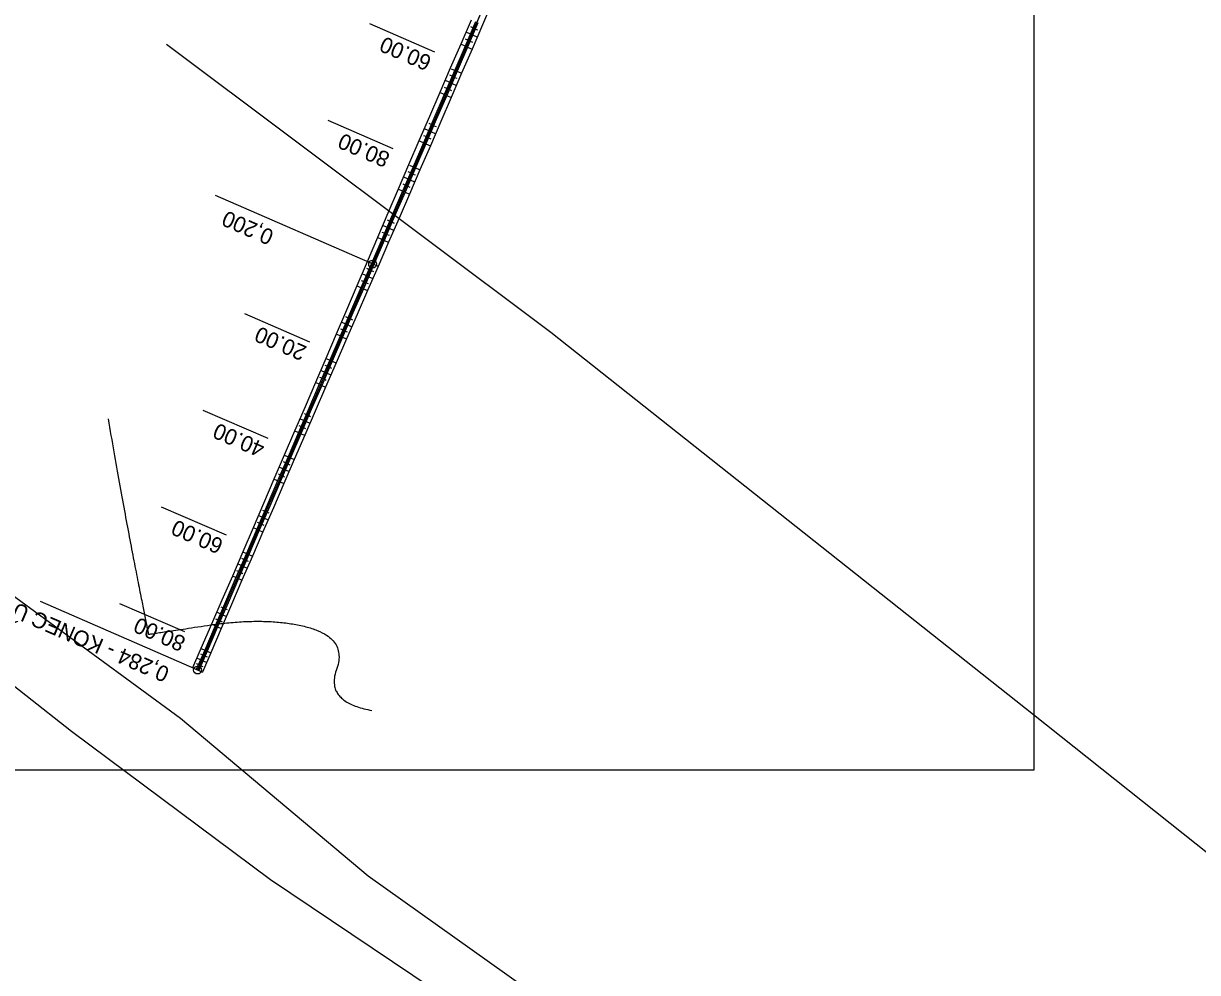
# Model space of a CAD drawing. Extents: x -495905 to -478420, y -1113297 to -1107716.
# Drawn here: x -480652.7 to -480429.6, y -1112691.6 to -1112511.2 of the extents above; entities that cross this region are included whole.
import ezdxf

# ---------------------------------------------------------------- set-up
doc = ezdxf.new("R2010")
doc.units = 0
for name, color, linetype in [('05_VHO_PŘÍKOP_NÁVRH', 7, 'Continuous'), ('2D_VRSTEVNICE', 7, 'Continuous'), ('Implicitní', 7, 'Continuous'), ('O6_HATCH_SLOPE_L', 7, 'Continuous'), ('O6_HATCH_SLOPE_R', 7, 'Continuous'), ('O6_HECTOMETRY', 7, 'Continuous'), ('O6_HLBODY', 7, 'Continuous'), ('O6_HRANA_TELESO', 7, 'Continuous'), ('O6_OSA', 7, 'Continuous'), ('O6_STANICENI', 7, 'Continuous'), ('O6_VOZOVKA', 7, 'Continuous'), ('O6_ZPEVKRAJ', 7, 'Continuous'), ('ODVODNĚNÍ PLOŠNÉ', 7, 'Continuous'), ('zamereni', 7, 'Continuous')]:
    doc.layers.add(name, color=color, linetype=linetype)

msp = doc.modelspace()

# ---------------------------------------------------------------- linework, layer by layer
at = {"layer": '05_VHO_PŘÍKOP_NÁVRH'}
msp.add_lwpolyline([(-480509.98, -1112372.25), (-480517.54, -1112397.37), (-480619.64, -1112634.1)], dxfattribs=at)
at = {"layer": '2D_VRSTEVNICE'}
msp.add_open_spline([(-480636.65, -1112586.38), (-480633.52, -1112604.4), (-480628.99, -1112627.3), (-480628.99, -1112627.3), (-480628.99, -1112627.3), (-480628.99, -1112627.3), (-480606.33, -1112623.9), (-480591.03, -1112628.04), (-480595.46, -1112640.12), (-480586.52, -1112641.78)], degree=2, dxfattribs=at)
at = {"layer": 'Implicitní'}
msp.add_lwpolyline([(-480696.42, -1112347.24), (-480460.69, -1112347.24), (-480460.69, -1112653.1), (-480696.42, -1112653.1)], close=True, dxfattribs=at)
at = {"layer": 'O6_HATCH_SLOPE_L'}
for p, q in [((-480567.31, -1112513.43), (-480566.48, -1112513.79)), ((-480566.82, -1112512.28), (-480566.4, -1112512.46)), ((-480565.98, -1112512.64), (-480565.98, -1112512.64)), ((-480568.3, -1112515.72), (-480567.46, -1112516.08)), ((-480567.81, -1112514.58), (-480567.39, -1112514.76)), ((-480566.97, -1112514.94), (-480566.97, -1112514.94)), ((-480571.27, -1112522.61), (-480570.42, -1112522.98)), ((-480570.78, -1112521.46), (-480570.35, -1112521.64)), ((-480569.93, -1112521.83), (-480569.93, -1112521.83)), ((-480572.26, -1112524.91), (-480571.41, -1112525.27)), ((-480571.77, -1112523.76), (-480571.34, -1112523.94)), ((-480570.92, -1112524.12), (-480570.92, -1112524.12)), ((-480574.74, -1112530.65), (-480574.31, -1112530.83)), ((-480573.89, -1112531.01), (-480573.89, -1112531.01)), ((-480575.73, -1112532.94), (-480575.3, -1112533.12)), ((-480575.23, -1112531.79), (-480574.38, -1112532.16)), ((-480574.88, -1112533.31), (-480574.88, -1112533.31)), ((-480576.22, -1112534.09), (-480575.38, -1112534.45)), ((-480578.7, -1112539.83), (-480578.28, -1112540.01)), ((-480577.86, -1112540.19), (-480577.86, -1112540.19)), ((-480579.69, -1112542.12), (-480579.27, -1112542.3)), ((-480579.19, -1112540.98), (-480578.35, -1112541.34)), ((-480578.85, -1112542.48), (-480578.85, -1112542.48)), ((-480580.18, -1112543.27), (-480579.35, -1112543.63)), ((-480582.66, -1112549.01), (-480582.25, -1112549.19)), ((-480581.83, -1112549.36), (-480581.83, -1112549.36)), ((-480583.65, -1112551.3), (-480583.24, -1112551.48)), ((-480583.15, -1112550.16), (-480582.33, -1112550.51)), ((-480582.83, -1112551.66), (-480582.83, -1112551.66)), ((-480584.14, -1112552.45), (-480583.33, -1112552.8)), ((-480586.62, -1112558.19), (-480586.22, -1112558.36)), ((-480587.61, -1112560.49), (-480587.21, -1112560.66)), ((-480587.11, -1112559.34), (-480586.32, -1112559.68)), ((-480585.82, -1112558.53), (-480585.82, -1112558.53)), ((-480588.1, -1112561.64), (-480587.32, -1112561.97)), ((-480586.82, -1112560.83), (-480586.82, -1112560.83)), ((-480591.07, -1112568.52), (-480590.31, -1112568.85)), ((-480590.58, -1112567.37), (-480590.2, -1112567.54)), ((-480589.81, -1112567.71), (-480589.81, -1112567.71)), ((-480592.06, -1112570.82), (-480591.31, -1112571.14)), ((-480591.57, -1112569.67), (-480591.19, -1112569.83)), ((-480590.81, -1112570), (-480590.81, -1112570)), ((-480595.03, -1112577.7), (-480594.29, -1112578.02)), ((-480594.54, -1112576.56), (-480594.17, -1112576.72)), ((-480593.8, -1112576.88), (-480593.8, -1112576.88)), ((-480596.02, -1112580), (-480595.29, -1112580.32)), ((-480595.53, -1112578.85), (-480595.16, -1112579.01)), ((-480594.79, -1112579.17), (-480594.79, -1112579.17)), ((-480598.99, -1112586.89), (-480598.27, -1112587.2)), ((-480598.5, -1112585.74), (-480598.14, -1112585.9)), ((-480597.77, -1112586.05), (-480597.77, -1112586.05)), ((-480599.98, -1112589.18), (-480599.27, -1112589.49)), ((-480599.49, -1112588.03), (-480599.13, -1112588.19)), ((-480598.77, -1112588.35), (-480598.77, -1112588.35)), ((-480602.95, -1112596.07), (-480602.25, -1112596.37)), ((-480602.46, -1112594.92), (-480602.1, -1112595.07)), ((-480601.75, -1112595.23), (-480601.75, -1112595.23)), ((-480603.94, -1112598.36), (-480603.24, -1112598.67)), ((-480603.45, -1112597.22), (-480603.1, -1112597.37)), ((-480602.74, -1112597.52), (-480602.74, -1112597.52)), ((-480606.92, -1112605.25), (-480606.23, -1112605.55)), ((-480606.42, -1112604.1), (-480606.07, -1112604.25)), ((-480605.73, -1112604.4), (-480605.73, -1112604.4)), ((-480607.41, -1112606.4), (-480607.07, -1112606.55)), ((-480606.72, -1112606.7), (-480606.72, -1112606.7)), ((-480607.91, -1112607.55), (-480607.22, -1112607.84)), ((-480610.38, -1112613.29), (-480610.04, -1112613.43)), ((-480609.71, -1112613.58), (-480609.71, -1112613.58)), ((-480611.37, -1112615.58), (-480611.03, -1112615.73)), ((-480610.88, -1112614.43), (-480610.2, -1112614.73)), ((-480610.7, -1112615.87), (-480610.7, -1112615.87)), ((-480611.86, -1112616.73), (-480611.19, -1112617.02)), ((-480614.34, -1112622.47), (-480613.99, -1112622.62)), ((-480613.65, -1112622.77), (-480613.65, -1112622.77)), ((-480615.33, -1112624.76), (-480614.98, -1112624.91)), ((-480614.84, -1112623.62), (-480614.14, -1112623.92)), ((-480614.63, -1112625.06), (-480614.63, -1112625.06)), ((-480615.83, -1112625.91), (-480615.12, -1112626.22)), ((-480618.2, -1112631.43), (-480617.84, -1112631.58)), ((-480617.48, -1112631.74), (-480617.48, -1112631.74)), ((-480619.4, -1112634.19), (-480618.67, -1112634.51)), ((-480619, -1112633.27), (-480618.64, -1112633.43)), ((-480618.6, -1112632.35), (-480617.88, -1112632.66)), ((-480618.27, -1112633.58), (-480618.27, -1112633.58))]:
    msp.add_line(p, q, dxfattribs=at)
at = {"layer": 'O6_HATCH_SLOPE_R'}
for p, q in [((-480567.79, -1112513.22), (-480568.62, -1112512.86)), ((-480568.13, -1112511.72), (-480568.13, -1112511.72)), ((-480567.29, -1112512.07), (-480567.71, -1112511.89)), ((-480568.78, -1112515.52), (-480569.62, -1112515.16)), ((-480569.12, -1112514.01), (-480569.12, -1112514.01)), ((-480568.28, -1112514.37), (-480568.7, -1112514.19)), ((-480571.75, -1112522.4), (-480572.6, -1112522.04)), ((-480572.1, -1112520.89), (-480572.1, -1112520.89)), ((-480571.25, -1112521.26), (-480571.68, -1112521.07)), ((-480572.74, -1112524.7), (-480573.59, -1112524.33)), ((-480573.09, -1112523.19), (-480573.09, -1112523.19)), ((-480572.24, -1112523.55), (-480572.67, -1112523.37)), ((-480575.71, -1112531.59), (-480576.56, -1112531.22)), ((-480576.07, -1112530.07), (-480576.07, -1112530.07)), ((-480575.22, -1112530.44), (-480575.64, -1112530.26)), ((-480576.7, -1112533.88), (-480577.55, -1112533.52)), ((-480577.05, -1112532.37), (-480577.05, -1112532.37)), ((-480576.21, -1112532.73), (-480576.63, -1112532.55)), ((-480579.67, -1112540.77), (-480580.51, -1112540.41)), ((-480580.02, -1112539.26), (-480580.02, -1112539.26)), ((-480579.17, -1112539.62), (-480579.6, -1112539.44)), ((-480580.66, -1112543.06), (-480581.5, -1112542.7)), ((-480581, -1112541.56), (-480581, -1112541.56)), ((-480580.17, -1112541.92), (-480580.58, -1112541.74)), ((-480583.96, -1112548.45), (-480583.96, -1112548.45)), ((-480583.14, -1112548.8), (-480583.55, -1112548.63)), ((-480584.94, -1112550.75), (-480584.94, -1112550.75)), ((-480584.12, -1112551.1), (-480584.53, -1112550.92)), ((-480583.63, -1112549.95), (-480584.45, -1112549.6)), ((-480584.62, -1112552.25), (-480585.43, -1112551.9)), ((-480587.89, -1112557.64), (-480587.89, -1112557.64)), ((-480587.1, -1112557.99), (-480587.49, -1112557.81)), ((-480588.88, -1112559.94), (-480588.88, -1112559.94)), ((-480588.09, -1112560.28), (-480588.48, -1112560.11)), ((-480587.59, -1112559.13), (-480588.38, -1112558.79)), ((-480588.58, -1112561.43), (-480589.37, -1112561.09)), ((-480591.82, -1112566.84), (-480591.82, -1112566.84)), ((-480591.06, -1112567.17), (-480591.44, -1112567)), ((-480592.81, -1112569.14), (-480592.81, -1112569.14)), ((-480592.05, -1112569.46), (-480592.43, -1112569.3)), ((-480591.55, -1112568.32), (-480592.31, -1112567.99)), ((-480592.54, -1112570.61), (-480593.3, -1112570.29)), ((-480595.76, -1112576.03), (-480595.76, -1112576.03)), ((-480595.02, -1112576.35), (-480595.39, -1112576.19)), ((-480596.75, -1112578.33), (-480596.75, -1112578.33)), ((-480596.01, -1112578.65), (-480596.38, -1112578.49)), ((-480595.51, -1112577.5), (-480596.25, -1112577.18)), ((-480596.5, -1112579.79), (-480597.24, -1112579.48)), ((-480599.47, -1112586.68), (-480600.2, -1112586.37)), ((-480599.7, -1112585.22), (-480599.7, -1112585.22)), ((-480598.98, -1112585.53), (-480599.34, -1112585.38)), ((-480600.46, -1112588.98), (-480601.18, -1112588.67)), ((-480600.69, -1112587.52), (-480600.69, -1112587.52)), ((-480599.97, -1112587.83), (-480600.33, -1112587.67)), ((-480603.43, -1112595.86), (-480604.14, -1112595.56)), ((-480603.65, -1112594.41), (-480603.65, -1112594.41)), ((-480602.94, -1112594.72), (-480603.29, -1112594.56)), ((-480604.42, -1112598.16), (-480605.13, -1112597.85)), ((-480604.63, -1112596.71), (-480604.63, -1112596.71)), ((-480603.93, -1112597.01), (-480604.28, -1112596.86)), ((-480607.39, -1112605.05), (-480608.08, -1112604.75)), ((-480607.59, -1112603.6), (-480607.59, -1112603.6)), ((-480606.9, -1112603.9), (-480607.24, -1112603.75)), ((-480608.38, -1112607.34), (-480609.07, -1112607.05)), ((-480608.58, -1112605.9), (-480608.58, -1112605.9)), ((-480607.89, -1112606.19), (-480608.23, -1112606.04)), ((-480611.35, -1112614.23), (-480612.02, -1112613.94)), ((-480611.53, -1112612.79), (-480611.53, -1112612.79)), ((-480610.86, -1112613.08), (-480611.19, -1112612.93)), ((-480612.34, -1112616.52), (-480613.01, -1112616.24)), ((-480612.52, -1112615.09), (-480612.52, -1112615.09)), ((-480611.85, -1112615.38), (-480612.18, -1112615.23)), ((-480615.31, -1112623.41), (-480615.99, -1112623.12)), ((-480615.49, -1112621.97), (-480615.49, -1112621.97)), ((-480614.82, -1112622.26), (-480615.16, -1112622.12)), ((-480616.49, -1112624.26), (-480616.49, -1112624.26)), ((-480615.81, -1112624.56), (-480616.15, -1112624.41)), ((-480616.3, -1112625.71), (-480616.99, -1112625.41)), ((-480619.08, -1112632.14), (-480619.79, -1112631.84)), ((-480619.39, -1112630.92), (-480619.39, -1112630.92)), ((-480618.68, -1112631.22), (-480619.03, -1112631.07)), ((-480619.88, -1112633.99), (-480620.59, -1112633.68)), ((-480620.19, -1112632.76), (-480620.19, -1112632.76)), ((-480619.48, -1112633.07), (-480619.83, -1112632.91))]:
    msp.add_line(p, q, dxfattribs=at)
at = {"layer": 'O6_HECTOMETRY'}
msp.add_circle((-480586.36, -1112556.94), 0.75, dxfattribs=at)
at = {"layer": 'O6_HLBODY'}
for p, q in [((-480585.39, -1112557.35), (-480616.24, -1112543.93)), ((-480618.67, -1112634.51), (-480649.51, -1112621.09))]:
    msp.add_line(p, q, dxfattribs=at)
msp.add_circle((-480619.64, -1112634.1), 0.75, dxfattribs=at)
at = {"layer": 'O6_HRANA_TELESO'}
for p, q in [((-480563.52, -1112506.9), (-480565.49, -1112511.49)), ((-480567.63, -1112510.57), (-480569.62, -1112515.16)), ((-480565.49, -1112511.49), (-480567.46, -1112516.08)), ((-480569.62, -1112515.16), (-480571.6, -1112519.74)), ((-480567.46, -1112516.08), (-480569.44, -1112520.68)), ((-480571.6, -1112519.74), (-480573.59, -1112524.33)), ((-480569.44, -1112520.68), (-480571.41, -1112525.27)), ((-480573.59, -1112524.33), (-480575.57, -1112528.92)), ((-480571.41, -1112525.27), (-480573.39, -1112529.86)), ((-480575.57, -1112528.92), (-480577.55, -1112533.52)), ((-480573.39, -1112529.86), (-480575.38, -1112534.45)), ((-480577.55, -1112533.52), (-480579.52, -1112538.11)), ((-480575.38, -1112534.45), (-480577.36, -1112539.04)), ((-480579.52, -1112538.11), (-480581.5, -1112542.7)), ((-480577.36, -1112539.04), (-480579.35, -1112543.63)), ((-480581.5, -1112542.7), (-480583.47, -1112547.3)), ((-480579.35, -1112543.63), (-480581.34, -1112548.22)), ((-480583.47, -1112547.3), (-480585.43, -1112551.9)), ((-480581.34, -1112548.22), (-480583.33, -1112552.8)), ((-480585.43, -1112551.9), (-480587.4, -1112556.49)), ((-480583.33, -1112552.8), (-480585.32, -1112557.39)), ((-480587.4, -1112556.49), (-480589.37, -1112561.09)), ((-480585.32, -1112557.39), (-480587.32, -1112561.97)), ((-480589.37, -1112561.09), (-480591.33, -1112565.69)), ((-480587.32, -1112561.97), (-480589.31, -1112566.56)), ((-480591.33, -1112565.69), (-480593.3, -1112570.29)), ((-480589.31, -1112566.56), (-480591.31, -1112571.14)), ((-480593.3, -1112570.29), (-480595.27, -1112574.88)), ((-480591.31, -1112571.14), (-480593.3, -1112575.73)), ((-480595.27, -1112574.88), (-480597.24, -1112579.48)), ((-480593.3, -1112575.73), (-480595.29, -1112580.32)), ((-480597.24, -1112579.48), (-480599.21, -1112584.07)), ((-480595.29, -1112580.32), (-480597.28, -1112584.91)), ((-480599.21, -1112584.07), (-480601.18, -1112588.67)), ((-480597.28, -1112584.91), (-480599.27, -1112589.49)), ((-480601.18, -1112588.67), (-480603.15, -1112593.26)), ((-480599.27, -1112589.49), (-480601.25, -1112594.08)), ((-480603.15, -1112593.26), (-480605.13, -1112597.85)), ((-480601.25, -1112594.08), (-480603.24, -1112598.67)), ((-480605.13, -1112597.85), (-480607.1, -1112602.45)), ((-480603.24, -1112598.67), (-480605.23, -1112603.26)), ((-480607.1, -1112602.45), (-480609.07, -1112607.05)), ((-480605.23, -1112603.26), (-480607.22, -1112607.84)), ((-480609.07, -1112607.05), (-480611.04, -1112611.64)), ((-480607.22, -1112607.84), (-480609.21, -1112612.43)), ((-480611.04, -1112611.64), (-480613.01, -1112616.24)), ((-480609.21, -1112612.43), (-480611.19, -1112617.02)), ((-480613.01, -1112616.24), (-480615, -1112620.82)), ((-480611.19, -1112617.02), (-480613.16, -1112621.62)), ((-480615, -1112620.82), (-480616.99, -1112625.41)), ((-480613.16, -1112621.62), (-480615.12, -1112626.22)), ((-480616.99, -1112625.41), (-480618.99, -1112629.99)), ((-480615.12, -1112626.22), (-480617.09, -1112630.81)), ((-480618.99, -1112629.99), (-480620.59, -1112633.68)), ((-480617.09, -1112630.81), (-480618.67, -1112634.51))]:
    msp.add_line(p, q, dxfattribs=at)
at = {"layer": 'O6_OSA'}
msp.add_line((-480519.82, -1112402.65), (-480619.64, -1112634.1), dxfattribs=at)
at = {"layer": 'O6_STANICENI'}
for p, q in [((-480574.52, -1112516.66), (-480586.92, -1112511.32)), ((-480571.44, -1112519.82), (-480569.6, -1112520.61)), ((-480582.44, -1112535.03), (-480594.84, -1112529.68)), ((-480579.36, -1112538.18), (-480577.52, -1112538.97)), ((-480598.29, -1112571.76), (-480610.68, -1112566.41)), ((-480595.2, -1112574.91), (-480593.36, -1112575.7)), ((-480606.21, -1112590.12), (-480618.6, -1112584.78)), ((-480603.12, -1112593.27), (-480601.29, -1112594.07)), ((-480614.13, -1112608.49), (-480626.52, -1112603.14)), ((-480611.04, -1112611.64), (-480609.21, -1112612.43)), ((-480622.05, -1112626.85), (-480634.44, -1112621.51)), ((-480618.96, -1112630), (-480617.13, -1112630.8)), ((-480620.55, -1112633.7), (-480618.72, -1112634.49))]:
    msp.add_line(p, q, dxfattribs=at)
at = {"layer": 'O6_VOZOVKA'}
for p, q in [((-480566.79, -1112510.93), (-480568.77, -1112515.52)), ((-480566.33, -1112511.13), (-480568.31, -1112515.72)), ((-480568.77, -1112515.52), (-480570.75, -1112520.11)), ((-480568.31, -1112515.72), (-480570.29, -1112520.31)), ((-480570.75, -1112520.11), (-480572.73, -1112524.7)), ((-480570.29, -1112520.31), (-480572.27, -1112524.9)), ((-480572.73, -1112524.7), (-480574.71, -1112529.29)), ((-480572.27, -1112524.9), (-480574.25, -1112529.49)), ((-480574.71, -1112529.29), (-480576.69, -1112533.89)), ((-480574.25, -1112529.49), (-480576.23, -1112534.08)), ((-480576.69, -1112533.89), (-480578.67, -1112538.48)), ((-480576.23, -1112534.08), (-480578.21, -1112538.68)), ((-480578.67, -1112538.48), (-480580.65, -1112543.07)), ((-480578.21, -1112538.68), (-480580.19, -1112543.27)), ((-480580.65, -1112543.07), (-480582.63, -1112547.66)), ((-480580.19, -1112543.27), (-480582.17, -1112547.86)), ((-480582.63, -1112547.66), (-480584.61, -1112552.25)), ((-480582.17, -1112547.86), (-480584.15, -1112552.45)), ((-480584.61, -1112552.25), (-480586.59, -1112556.84)), ((-480584.15, -1112552.45), (-480586.13, -1112557.04)), ((-480586.59, -1112556.84), (-480588.57, -1112561.43)), ((-480586.13, -1112557.04), (-480588.11, -1112561.63)), ((-480588.57, -1112561.43), (-480590.55, -1112566.02)), ((-480588.11, -1112561.63), (-480590.09, -1112566.22)), ((-480590.55, -1112566.02), (-480592.53, -1112570.62)), ((-480590.09, -1112566.22), (-480592.07, -1112570.81)), ((-480592.53, -1112570.62), (-480594.51, -1112575.21)), ((-480592.07, -1112570.81), (-480594.05, -1112575.41)), ((-480594.51, -1112575.21), (-480596.49, -1112579.8)), ((-480594.05, -1112575.41), (-480596.03, -1112580)), ((-480596.49, -1112579.8), (-480598.47, -1112584.39)), ((-480596.03, -1112580), (-480598.01, -1112584.59)), ((-480598.47, -1112584.39), (-480600.45, -1112588.98)), ((-480598.01, -1112584.59), (-480599.99, -1112589.18)), ((-480600.45, -1112588.98), (-480602.43, -1112593.57)), ((-480599.99, -1112589.18), (-480601.97, -1112593.77)), ((-480602.43, -1112593.57), (-480604.41, -1112598.16)), ((-480601.97, -1112593.77), (-480603.95, -1112598.36)), ((-480604.41, -1112598.16), (-480606.39, -1112602.75)), ((-480603.95, -1112598.36), (-480605.93, -1112602.95)), ((-480606.39, -1112602.75), (-480608.37, -1112607.34)), ((-480605.93, -1112602.95), (-480607.91, -1112607.54)), ((-480608.37, -1112607.34), (-480610.35, -1112611.94)), ((-480607.91, -1112607.54), (-480609.89, -1112612.13)), ((-480610.35, -1112611.94), (-480612.33, -1112616.53)), ((-480609.89, -1112612.13), (-480611.87, -1112616.73)), ((-480612.33, -1112616.53), (-480614.31, -1112621.12)), ((-480611.87, -1112616.73), (-480613.85, -1112621.32)), ((-480614.31, -1112621.12), (-480616.29, -1112625.71)), ((-480613.85, -1112621.32), (-480615.84, -1112625.91)), ((-480616.29, -1112625.71), (-480618.27, -1112630.3)), ((-480615.84, -1112625.91), (-480617.82, -1112630.5)), ((-480618.27, -1112630.3), (-480619.87, -1112633.99)), ((-480617.82, -1112630.5), (-480619.41, -1112634.19))]:
    msp.add_line(p, q, dxfattribs=at)
at = {"layer": 'O6_ZPEVKRAJ'}
for p, q in [((-480566.79, -1112510.93), (-480568.77, -1112515.52)), ((-480566.33, -1112511.13), (-480568.31, -1112515.72)), ((-480568.77, -1112515.52), (-480570.75, -1112520.11)), ((-480568.31, -1112515.72), (-480570.29, -1112520.31)), ((-480570.75, -1112520.11), (-480572.73, -1112524.7)), ((-480570.29, -1112520.31), (-480572.27, -1112524.9)), ((-480572.73, -1112524.7), (-480574.71, -1112529.29)), ((-480572.27, -1112524.9), (-480574.25, -1112529.49)), ((-480574.71, -1112529.29), (-480576.69, -1112533.89)), ((-480574.25, -1112529.49), (-480576.23, -1112534.08)), ((-480576.69, -1112533.89), (-480578.67, -1112538.48)), ((-480576.23, -1112534.08), (-480578.21, -1112538.68)), ((-480578.67, -1112538.48), (-480580.65, -1112543.07)), ((-480578.21, -1112538.68), (-480580.19, -1112543.27)), ((-480580.65, -1112543.07), (-480582.63, -1112547.66)), ((-480580.19, -1112543.27), (-480582.17, -1112547.86)), ((-480582.63, -1112547.66), (-480584.61, -1112552.25)), ((-480582.17, -1112547.86), (-480584.15, -1112552.45)), ((-480584.61, -1112552.25), (-480586.59, -1112556.84)), ((-480584.15, -1112552.45), (-480586.13, -1112557.04)), ((-480586.59, -1112556.84), (-480588.57, -1112561.43)), ((-480586.13, -1112557.04), (-480588.11, -1112561.63)), ((-480588.57, -1112561.43), (-480590.55, -1112566.02)), ((-480588.11, -1112561.63), (-480590.09, -1112566.22)), ((-480590.55, -1112566.02), (-480592.53, -1112570.62)), ((-480590.09, -1112566.22), (-480592.07, -1112570.81)), ((-480592.53, -1112570.62), (-480594.51, -1112575.21)), ((-480592.07, -1112570.81), (-480594.05, -1112575.41)), ((-480594.51, -1112575.21), (-480596.49, -1112579.8)), ((-480594.05, -1112575.41), (-480596.03, -1112580)), ((-480596.49, -1112579.8), (-480598.47, -1112584.39)), ((-480596.03, -1112580), (-480598.01, -1112584.59)), ((-480598.47, -1112584.39), (-480600.45, -1112588.98)), ((-480598.01, -1112584.59), (-480599.99, -1112589.18)), ((-480600.45, -1112588.98), (-480602.43, -1112593.57)), ((-480599.99, -1112589.18), (-480601.97, -1112593.77)), ((-480602.43, -1112593.57), (-480604.41, -1112598.16)), ((-480601.97, -1112593.77), (-480603.95, -1112598.36)), ((-480604.41, -1112598.16), (-480606.39, -1112602.75)), ((-480603.95, -1112598.36), (-480605.93, -1112602.95)), ((-480606.39, -1112602.75), (-480608.37, -1112607.34)), ((-480605.93, -1112602.95), (-480607.91, -1112607.54)), ((-480608.37, -1112607.34), (-480610.35, -1112611.94)), ((-480607.91, -1112607.54), (-480609.89, -1112612.13)), ((-480610.35, -1112611.94), (-480612.33, -1112616.53)), ((-480609.89, -1112612.13), (-480611.87, -1112616.73)), ((-480612.33, -1112616.53), (-480614.31, -1112621.12)), ((-480611.87, -1112616.73), (-480613.85, -1112621.32)), ((-480614.31, -1112621.12), (-480616.29, -1112625.71)), ((-480613.85, -1112621.32), (-480615.84, -1112625.91)), ((-480616.29, -1112625.71), (-480618.27, -1112630.3)), ((-480615.84, -1112625.91), (-480617.82, -1112630.5)), ((-480618.27, -1112630.3), (-480619.87, -1112633.99)), ((-480617.82, -1112630.5), (-480619.41, -1112634.19))]:
    msp.add_line(p, q, dxfattribs=at)
at = {"layer": 'ODVODNĚNÍ PLOŠNÉ'}
for points in [[(-480683.24, -1112184.91), (-480705.82, -1112170.51), (-480724.73, -1112199.29), (-480740.02, -1112226.69), (-480770.07, -1112280.48), (-480787.56, -1112272.65), (-480804.66, -1112307.36), (-480823.55, -1112348.87), (-480840.47, -1112372.38), (-480856.03, -1112400.02), (-480883.75, -1112452.88), (-480858.24, -1112477.07), (-480826.29, -1112498.96), (-480790.36, -1112523.05), (-480746.16, -1112556.89), (-480709.51, -1112582.28), (-480664.42, -1112612.84), (-480622.89, -1112643.26), (-480587.18, -1112673.2), (-480554.27, -1112696.66)], [(-480567.11, -1112699.96), (-480605.77, -1112673.98), (-480643.58, -1112645.75), (-480678.37, -1112618.39), (-480715.87, -1112588.9), (-480749.35, -1112567.2), (-480787.89, -1112538.17), (-480825.55, -1112512.74), (-480861.4, -1112486.36), (-480890.78, -1112463.8), (-480913.93, -1112510.23), (-480932.39, -1112553.8), (-480954.71, -1112598.73), (-480984.47, -1112651.77), (-481010.43, -1112698.6)]]:
    msp.add_lwpolyline(points, dxfattribs=at)
at = {"layer": 'zamereni'}
for p, q in [((-480625.52, -1112515.14), (-480552.5, -1112569.89)), ((-480552.5, -1112569.89), (-480460.73, -1112642.55)), ((-480460.73, -1112642.55), (-480349.91, -1112730.78))]:
    msp.add_line(p, q, dxfattribs=at)

# ---------------------------------------------------------------- texts
at = {"layer": 'Implicitní'}
msp.add_text('0,200', height=3, rotation=156.49, dxfattribs=at).set_placement((-480604.91, -1112550.7))
at = {"layer": 'O6_HLBODY'}
msp.add_text('0,284 - KONEC ÚPRAVY', height=3, rotation=156.6698, dxfattribs=at).set_placement((-480624.76, -1112633.78))
at = {"layer": 'O6_STANICENI'}
for s, p in [('60.00', (-480574.92, -1112517.58)), ('80.00', (-480582.84, -1112535.95)), ('20.00', (-480598.68, -1112572.68)), ('40.00', (-480606.6, -1112591.04)), ('60.00', (-480614.52, -1112609.41)), ('80.00', (-480621.68, -1112627.95))]:
    msp.add_text(s, height=2.999, rotation=156.6698, dxfattribs=at).set_placement(p)

doc.saveas('drawing.dxf')
